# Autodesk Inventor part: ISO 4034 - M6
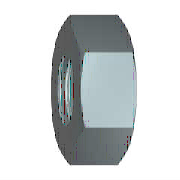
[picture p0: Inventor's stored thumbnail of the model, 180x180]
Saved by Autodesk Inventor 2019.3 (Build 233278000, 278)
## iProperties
Created: 2018-01
Part Number: ISO 4034 - M6
Material: Ocel
Description: Šestihranné matice. Výrobní řada C
Document SubType Name: Modeling
Standard: ISO 4034
Designer: B-hon
Standards Organization: CSN
Language: cs-CZ
Size Designation: M6
Categories: <MemberInstance><Categories><Category DisplayName="Spojovací materiál" InternalName="e4da775c-781d-43d5-af7c-5136215cf5a6" Mnemonic="FSTN"><Category DisplayName
Density: 7.85 g/cm^3
Appearance: Plech
IsCustomPart: 0
Author: B-hon
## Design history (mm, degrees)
sketch "Náčrt1"
  geometry: L1 (-5.774, 0)-(-2.887, 5); L2 (-2.887, 5)-(2.887, 5); L3 (2.887, 5)-(5.774, 0); L4 (5.774, 0)-(2.887, -5); L5 (2.887, -5)-(-2.887, -5); L6 (-2.887, -5)-(-5.774, 0); 2 further points
  constraints: 12 end point, 1 coincident, 1 horizontal, 11 other
  dimensions: "d0" = 11.54701 distance of L3.end L1.start (= 1.1547 x SW)
extrude "Těleso" new body sketch "Náčrt1" distance "d1" = 6.1 (= KOH); taper "d2" = 0 deg
sketch "Náčrt2"
  geometry: L1 (0, 2.887)-(0, 5.774) reference; L2 (0, 5.774)-(6.1, 5.774) reference; L3 (6.1, 2.887)-(6.1, 5.774) reference; L4 (-1.22, 0)-(7.32, 0) reference; L5 (0.447, 5.774)-(0, 5); L6 (5.653, 5.774)-(6.1, 5)
  constraints: 4 end point, 4 point on line
  dimensions: "d3" = 30 deg angle of L1 L5 (= ANG1); "d4" = 30 deg angle of L3 L6 (= ANG2); "d5" = 10 diameter of L5.end L4 (= SW0); "d6" = 10 diameter of L6.end L4 (= SW01)
revolve "Zkosení1" sketch "Náčrt2" stored, may be unused: angle "d7" = 90 deg
sketch "Náčrt3"
  geometry: A1 r 5 centre (0, 0) between (-2.5, -4.33) and (2.5, -4.33) reference; 1 further point
  constraints: 1 coincident
hole "Závit" sketch "Náčrt3" at (0, 0) diameter "d25" = 4.917; stored, may be unused: countersink angle "d29" = 82 deg, drill point angle "d31" = 118 deg; dims "d26" = 6, "d27" = 4, "d28" = 2, "d30" = 8
workaxis "Work Axis1"
workplane "Work Plane1"
body "Solid1"
chamfer "Zkosení2" distance "d8" = 0.54127 (= -0.5 x GD1 + 0.5 x NND); stored, may be unused: angle "d9" = 30 deg, second distance "d40" = 0.54127 (= -0.5 x GD1 + 0.5 x NND)
chamfer "Zkosení3" distance "d10" = 0.54127 (= -0.5 x GD1 + 0.5 x NND); stored, may be unused: angle "d11" = 30 deg, second distance "d41" = 0.54127 (= -0.5 x GD1 + 0.5 x NND)
other parameters: "ANG1" = 30 deg [user parameter; used in 1 equation term], "ANG2" = 30 deg [user parameter; used in 1 equation term], "NND" = 6 [user parameter; used in 4 equation terms], "KOH" = 6.1 [user parameter; used in 1 equation term], "SW0" = 10 (= SW) [user parameter; used in 1 equation term], "SW01" = 10 (= SW) [user parameter; used in 1 equation term], "GD1" = 4.91747 (computed from THREADDIA, PTC, TOA) [user parameter; used in 4 equation terms], "d13" = 0, "d14" = 0, "d39" = 0, "d42" = 0, "GUL" = 0.54127 (= 0.541266 x PTC) [user parameter], "THREADDIA" = 6 [user parameter; used in 1 equation term], "TOA" = 30 deg [user parameter; used in 1 equation term], "PTC" = 1 [user parameter; used in 4 equation terms], "E0" = 11.55 (= 1.155 x SW) [user parameter], "GAL" = 0.54127 (= 0.541266 x PTC) [user parameter]
